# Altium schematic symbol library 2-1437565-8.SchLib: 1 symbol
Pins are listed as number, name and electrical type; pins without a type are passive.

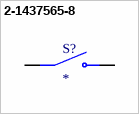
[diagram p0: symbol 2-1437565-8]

## 2-1437565-8
designator S?
MP: 2-1437565-8
footprint 2-1437565-8
pins: 1 COM, 2 COM, 3 NO, 4 NO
